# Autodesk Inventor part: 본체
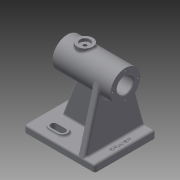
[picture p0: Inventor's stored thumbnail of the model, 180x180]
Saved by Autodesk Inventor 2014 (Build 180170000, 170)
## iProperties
Created: 2019-10
Part Number: 본체
Material: Generic
Document SubType Name: Modeling
Designer: kh
Density: 1 g/cm^3
Appearance: Default
Author: kh
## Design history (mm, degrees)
sketch "Sketch1"
  geometry: L1 (-50, -43)-(50, -43); L2 (50, -43)-(50, 43); L3 (50, 43)-(-50, 43); L4 (-50, 43)-(-50, -43); L5 (-50, -43)-(50, 43); L6 (50, -43)-(-50, 43); L7 (-24, 27)-(-12, 27); L8 (-24, 31.5)-(-12, 31.5); L9 (-12, 22.5)-(-24, 22.5); L10 (-24, -27)-(-12, -27); L11 (-24, -22.5)-(-12, -22.5); L12 (-12, -31.5)-(-24, -31.5); A1 r 4.5 centre (-24, 27) between (-24, 31.5) and (-24, 22.5); A2 r 4.5 centre (-12, 27) between (-12, 22.5) and (-12, 31.5); A3 r 4.5 centre (-24, -27) between (-24, -22.5) and (-24, -31.5); A4 r 4.5 centre (-12, -27) between (-12, -31.5) and (-12, -22.5); 3 further points
  constraints: 28 end point, 8 point on circle, 8 tangent, 6 parallel, 4 centre point, 4 midpoint, 1 horizontal, 1 perpendicular
  dimensions: "d0" = 100 distance of L3.end L2.end; "d1" = 86 distance of L2.end L1.end; "d2" = 27 distance from line of L7 point (0, 0); "d3" = 12 distance of L8.start L8.end; "d4" = 26 distance from line of L4 L8.start; "d5" = 9 distance between parallel lines of L9 L8; "d6" = 12 distance of L11.start L11.end; "d7" = 9 distance between parallel lines of L12 L11; "d9" = 26 distance from line of L4 L11.start; "d80" = 27 vertical distance of point (-18, -27) point (0, 0)
extrude "Extrusion1" new body sketch "Sketch1" distance "d10" = 10; taper "d11" = 0 deg
sketch "Sketch2"
  geometry: L1 (-24, 27)-(-12, 27); L2 (-24, 20)-(-12, 20); L3 (-12, 34)-(-24, 34); L4 (-24, -27)-(-12, -27); L5 (-24, -34)-(-12, -34); L6 (-12, -20)-(-24, -20); L7 (-24, 27)-(-12, 27); L8 (-24, 22.5)-(-12, 22.5); L9 (-12, 31.5)-(-24, 31.5); L10 (-24, -27)-(-12, -27); L11 (-24, -31.5)-(-12, -31.5); L12 (-12, -22.5)-(-24, -22.5); A1 r 4.5 centre (-24, 27) between (-24, 31.5) and (-24, 22.5) reference; A2 r 4.5 centre (-12, 27) between (-12, 22.5) and (-12, 31.5) reference; A3 r 4.5 centre (-24, -27) between (-24, -22.5) and (-24, -31.5) reference; A4 r 4.5 centre (-12, -27) between (-12, -31.5) and (-12, -22.5) reference; A5 r 7 centre (-24, 27) between (-24, 34) and (-24, 20); A6 r 7 centre (-12, 27) between (-12, 20) and (-12, 34); A7 r 7 centre (-24, -27) between (-24, -20) and (-24, -34); A8 r 7 centre (-12, -27) between (-12, -34) and (-12, -20); A9 r 4.5 centre (-24, 27) between (-24, 31.5) and (-24, 22.5); A10 r 4.5 centre (-12, 27) between (-12, 22.5) and (-12, 31.5); A11 r 4.5 centre (-24, -27) between (-24, -22.5) and (-24, -31.5); A12 r 4.5 centre (-12, -27) between (-12, -31.5) and (-12, -22.5); 5 further points
  constraints: 32 end point, 16 point on circle, 16 tangent, 8 centre point, 7 equal length, 4 midpoint, 1 horizontal
  dimensions: "d12" = 14 distance between parallel lines of L2 L3; "d13" = 14 distance between parallel lines of L5 L6; "d14" = 9 distance between parallel lines of L11 L12; "d15" = 9 distance between parallel lines of L9 L8
extrude "Extrusion2" join sketch "Sketch2" distance "d16" = 3; taper "d17" = 0 deg
sketch "Sketch3"
  geometry: L1 (32, 86)-(-30, 86); L2 (-30, 86)-(-30, 100.5); L3 (-30, 100.5)-(32, 100.5); L4 (32, 100.5)-(32, 86); L5 (-30, 86)-(-50, 86); L6 (-50, 86)-(-50, 97.5); L7 (-50, 97.5)-(-30, 97.5); L8 (-30, 97.5)-(-30, 86); L9 (32, 86)-(-50, 86); L10 (-50, 86)-(-50, 107); L11 (-50, 107)-(32, 107); L12 (32, 107)-(32, 86); L13 (-50, 0)-(-50, 10) reference; L14 (50, 0)-(-50, 0) reference; 5 further points
  constraints: 24 end point, 6 parallel, 4 midpoint, 3 horizontal, 3 perpendicular, 2 vertical alignment
  dimensions: "d18" = 29 diameter of L3 L1; "d19" = 23 diameter of L7 L5; "d20" = 42 diameter of L11 L5; "d21" = 82 distance of L10.end L11.end; "d22" = 62 distance of L2.end L3.end; "d23" = 86 distance from line of L1.start L14
revolve "Revolution1" sketch "Sketch3" stored, may be unused: angle "d24" = 90 deg
workplane "Work Plane1"
sketch "Sketch4"
  geometry: L1 (-32, 21)-(-32, -21) reference; C1 r 11 at (-7, 0); 2 further points
  constraints: 1 centre point, 1 coincident, 1 horizontal alignment, 1 midpoint
  dimensions: "d26" = 22 diameter of C1; "d79" = 25 distance from line of point (-7, 0) L1
extrude "Extrusion3" join sketch "Sketch4" stored distance "d27" = 3; taper "d28" = 0 deg
hole "Hole1" diameter "d31" = 4.917; stored, may be unused: countersink angle "d35" = 90 deg, drill point angle "d37" = 118 deg; dims "d29" = 10, "d30" = 10, "d32" = 6, "d33" = 14, "d34" = 4, "d36" = 8
sketch "Sketch6" dims "d39" = 36
  geometry: C1 r 21 at (0, 0) reference; 3 further points
  constraints: 1 coincident, 1 horizontal alignment, 2 other
hole "Hole2" sketch "Sketch6" at (18, 0) diameter "d40" = 2.459; stored, may be unused: countersink angle "d44" = 90 deg, drill point angle "d46" = 118 deg; dims "d41" = 8, "d42" = 14, "d43" = 4, "d45" = 10
pattern_circular "Circular Pattern1" dims angle "d48" = 360 deg
workplane "Work Plane2"
mirror "Mirror1"
fillet "Fillet1" dims "d50" = 3
fillet "Fillet2" dims "d51" = 3
fillet "Fillet3" dims "d52" = 3
workplane "Work Plane4"
sketch "Sketch8"
  geometry: L1 (-10, 0)-(-10, 80) reference; L2 (-7, 83)-(0, 83) reference; L3 (0, 83)-(0, -3) reference; L4 (0, -3)-(-7, -3) reference; L5 (-7.783, 82.896)-(-91.48, 60.272); L6 (-7.783, -2.896)-(-91.48, 19.728); L7 (-10, 80)-(-10, 0); C1 r 11.5 at (-86, 40) reference; A1 r 3 centre (-7, 80) between (-7, 83) and (-10, 80) reference; A2 r 3 centre (-7, 0) between (-10, 0) and (-7, -3) reference; A3 r 21 centre (-86, 40) between (-91.48, 60.272) and (-91.48, 19.728) reference; A4 r 21 centre (-86, 40) between (-91.48, 19.728) and (-91.48, 60.272); A5 r 3 centre (-7, 0) between (-10, 0) and (-7.783, -2.896); A6 r 3 centre (-7, 80) between (-7.783, 82.896) and (-10, 80); 1 further point
  constraints: 10 point on circle, 8 tangent, 6 end point, 3 centre point, 3 coincident, 1 collinear
extrude "Extrusion4" join sketch "Sketch8" distance "d56" = 10; taper "d57" = 0 deg
sketch "Sketch9"
  geometry: L1 (0, 106)-(4.542, 106) reference; L2 (4.542, 106)-(4.542, 100.5) reference; L3 (4.542, 100.5)-(-30, 100.5) reference; L4 (-30, 100.5)-(-30, 97.5) reference; L5 (-30, 97.5)-(-50, 97.5) reference; L6 (-50, 97.5)-(-50, 102.77) reference; L7 (-50, 102.77)-(-40, 102.77) reference; L8 (-40, 102.77)-(-39.261, 104) reference; L9 (-39.261, 104)-(-40, 105.229) reference; L10 (-40, 105.229)-(-50, 105.229) reference; L11 (-50, 105.229)-(-50, 107) reference; L12 (-50, 107)-(-4, 107) reference; L13 (-4, 107)-(-4, 110) reference; L14 (-4, 110)-(0, 110) reference; L15 (0, 110)-(0, 106) reference; L16 (9.459, 106)-(14, 106) reference; L17 (14, 106)-(14, 110) reference; L18 (14, 110)-(18, 110) reference; L19 (18, 110)-(18, 107) reference; L20 (18, 107)-(32, 107) reference; L21 (32, 107)-(32, 105.23) reference; L22 (32, 105.23)-(22, 105.23) reference; L23 (22, 105.23)-(21.261, 104) reference; L24 (21.261, 104)-(22, 102.771) reference; L25 (22, 102.771)-(32, 102.771) reference; L26 (32, 102.771)-(32, 100.5) reference; L27 (32, 100.5)-(9.459, 100.5) reference; L28 (9.459, 100.5)-(9.459, 106) reference; L29 (-30, 71.5)-(32, 71.5) reference; L30 (32, 71.5)-(32, 69.23) reference; L31 (32, 69.23)-(22, 69.23) reference; L32 (22, 69.23)-(21.261, 68) reference; L33 (21.261, 68)-(22, 66.77) reference; L34 (22, 66.77)-(32, 66.77) reference; L35 (32, 66.77)-(32, 65) reference; L36 (32, 65)-(-25, 65) reference; L37 (-25, 65)-(-25, 10) reference; L38 (-25, 10)-(47, 10) reference; L39 (50, 7)-(50, 0) reference; L40 (50, 0)-(-50, 0) reference; L41 (-50, 0)-(-50, 7) reference; L42 (-47, 10)-(-35, 10) reference; L43 (-35, 10)-(-35, 65) reference; L44 (-35, 65)-(-50, 65) reference; L45 (-50, 65)-(-50, 66.77) reference; L46 (-50, 66.77)-(-40, 66.77) reference; L47 (-40, 66.77)-(-39.261, 68) reference; L48 (-39.261, 68)-(-40, 69.229) reference; L49 (-40, 69.229)-(-50, 69.229) reference; L50 (-50, 69.229)-(-50, 74.5) reference; L51 (-50, 74.5)-(-30, 74.5) reference; L52 (-30, 74.5)-(-30, 71.5) reference; L53 (35, 10)-(20.959, 48.576); A1 r 3 centre (47, 7) between (50, 7) and (47, 10) reference; A2 r 3 centre (-47, 7) between (-47, 10) and (-50, 7) reference; 1 further point
  constraints: 2 end point, 1 point on line
  dimensions: "d58" = 70 deg angle of L38 L53; "d59" = 15 distance from line of L53.start L39
feature "Rib1" sketch "Sketch9" dims "d60" = 1, "d61" = 10, "d62" = 0, "d63" = 0, "d64" = 1, "d65" = 1
fillet "Fillet4" dims "d66" = 3
fillet "Fillet5" dims "d67" = 3
fillet "Fillet6" dims "d68" = 3
fillet "Fillet7" dims "d69" = 3
fillet "Fillet8" dims "d70" = 3
sketch "Sketch10"
  geometry: L1 (40.598, -15.156)-(40.598, 15.156); L2 (40.598, 15.156)-(45.402, 15.156); L3 (45.402, 15.156)-(45.402, -15.156); L4 (45.402, -15.156)-(40.598, -15.156); L5 (40.598, 15.156)-(45.402, -15.156); L6 (40.598, -15.156)-(45.402, 15.156); L7 (50, -40)-(50, 40) reference; L8 (47, 43)-(-47, 43) reference; 2 further points
  constraints: 4 end point, 1 midpoint, 2 other
  dimensions: "d71" = 7 distance from line of L7 point (43, 0); "d72" = 43 distance from line of L8 point (43, 0)
emboss "Emboss1" sketch "Sketch10" dims "d0" = 100, "d1" = 86, "d2" = 27, "d3" = 12, "d4" = 26, "d5" = 9, "d6" = 12, "d7" = 9, "d9" = 26, "d73" = 0.5, "d74" = 0, "d80" = 27
chamfer "Chamfer1" distance "d75" = 1; stored, may be unused: second distance "d76" = 2, angle "d77" = 45 deg
fillet "Fillet9" dims "d78" = 3
body "Solid1"
node "Project Cut Edges1"
node "Project Cut Edges2"
other parameters: "d55" = -15
